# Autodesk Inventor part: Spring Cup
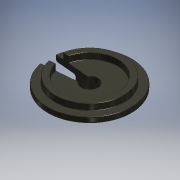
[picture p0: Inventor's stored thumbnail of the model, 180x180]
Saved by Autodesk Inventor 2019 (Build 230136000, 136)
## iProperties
Shininess: 50.0
Compacted: True
Length Units: 11272
Angle Units: 11279
Time Units: 11290
Mass Units: 11286
Length Display Precision: 4
Angle Display Precision: 2
Company: Autodesk
Created: 2000-03
Part Number: Spring Cup
Project: Inventor Samples
User Status: IN PROGRESS
Document SubType Name: Modeling
Designer: Autodesk, Inc.
Density: 1.13 g/cm^3
Mass: 0.4348 g
Surface Area: 6.80342 cm^2
Volume: 0.384779 cm^3
Material: Nylon-6/6
Appearance: Gunmetal
Density: 0.0
Volumn: 0.0
Area: 0.0
PropertySet Name: Model Information
Control State: 0
Master: False
Checked Out: False
Checked Out Date: 2018-05-30
Last Check In Date: 2018-05-30
Author: Autodesk, Inc.
Revision Number: A
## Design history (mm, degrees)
node "Revolution1" dims "d10" = 90 deg
  sketch "Sketch2"
    geometry: L1 (-6.24, 5.709)-(-6.24, -3.546); L2 (-9.224, -2.438)-(-9.224, 0.102); L3 (-9.224, 0.102)-(-7.891, 0.102); L4 (-7.891, 0.102)-(-7.891, 1.372); L5 (-7.891, 1.372)-(-11.955, 1.372); L6 (-11.955, 1.372)-(-11.955, 2.642); L7 (-11.955, 2.642)-(-13.225, 2.642); L8 (-13.225, 2.642)-(-13.225, 1.372); L9 (-13.225, 1.372)-(-14.812, 1.372); L10 (-14.812, 1.372)-(-14.812, 0.102); L11 (-14.812, 0.102)-(-10.494, 0.102); L12 (-10.494, 0.102)-(-10.494, -2.438); L13 (-10.494, -2.438)-(-9.224, -2.438)
    constraints: 26 end point, 10 parallel, 3 collinear, 1 perpendicular, 1 vertical, 1 other
    dimensions: "d0" = 13.97 diameter of L8 L1; "d1" = 1.27 distance of L6.end L7.end; "d2" = 1.27 distance from line of L7.end L9; "d3" = 2.54 distance between parallel lines of L13 L11; "d4" = 3.302 diameter of L4 L1; "d5" = 5.969 diameter of L2 L1; "d6" = 1.27 distance between parallel lines of L2 L12; "d7" = 17.145 diameter of L10 L1; "d8" = 11.43 diameter of L6 L1; "d9" = 1.27 distance between parallel lines of L9 L11
node "Fillet1" dims "d11" = 0.381
node "Extrusion1" dims "d15" = 25.4, "d16" = 0
  sketch "Sketch3"
    geometry: L1 (0, 0)-(-10.431, 0); L2 (-8.572, 1.544)-(-8.572, -1.544); L3 (-8.572, -1.544)-(0, -0.794); L4 (-8.572, 1.544)-(0, 0.794); L5 (0, 0.794)-(0, -0.794); C1 r 1.651 at (0, 0) reference; C2 r 5.715 at (0, 0) reference; C3 r 8.572 at (0, 0) reference
    constraints: 10 end point, 1 equal length, 1 horizontal, 1 midpoint, 1 perpendicular, 1 tangent, 1 vertical
    dimensions: "d12" = 10 deg angle of L3 L4; "d13" = 1.5875 distance of L4.end L3.end; "d14" = 0.79375 distance of C1.centre L3.end (= 0.5 x d13)
node "Fillet2" dims "d17" = 0.127
node "Fillet3" dims "d18" = 0.127
body "Solid1"
